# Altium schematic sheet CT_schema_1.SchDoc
size 594 x 458 mm
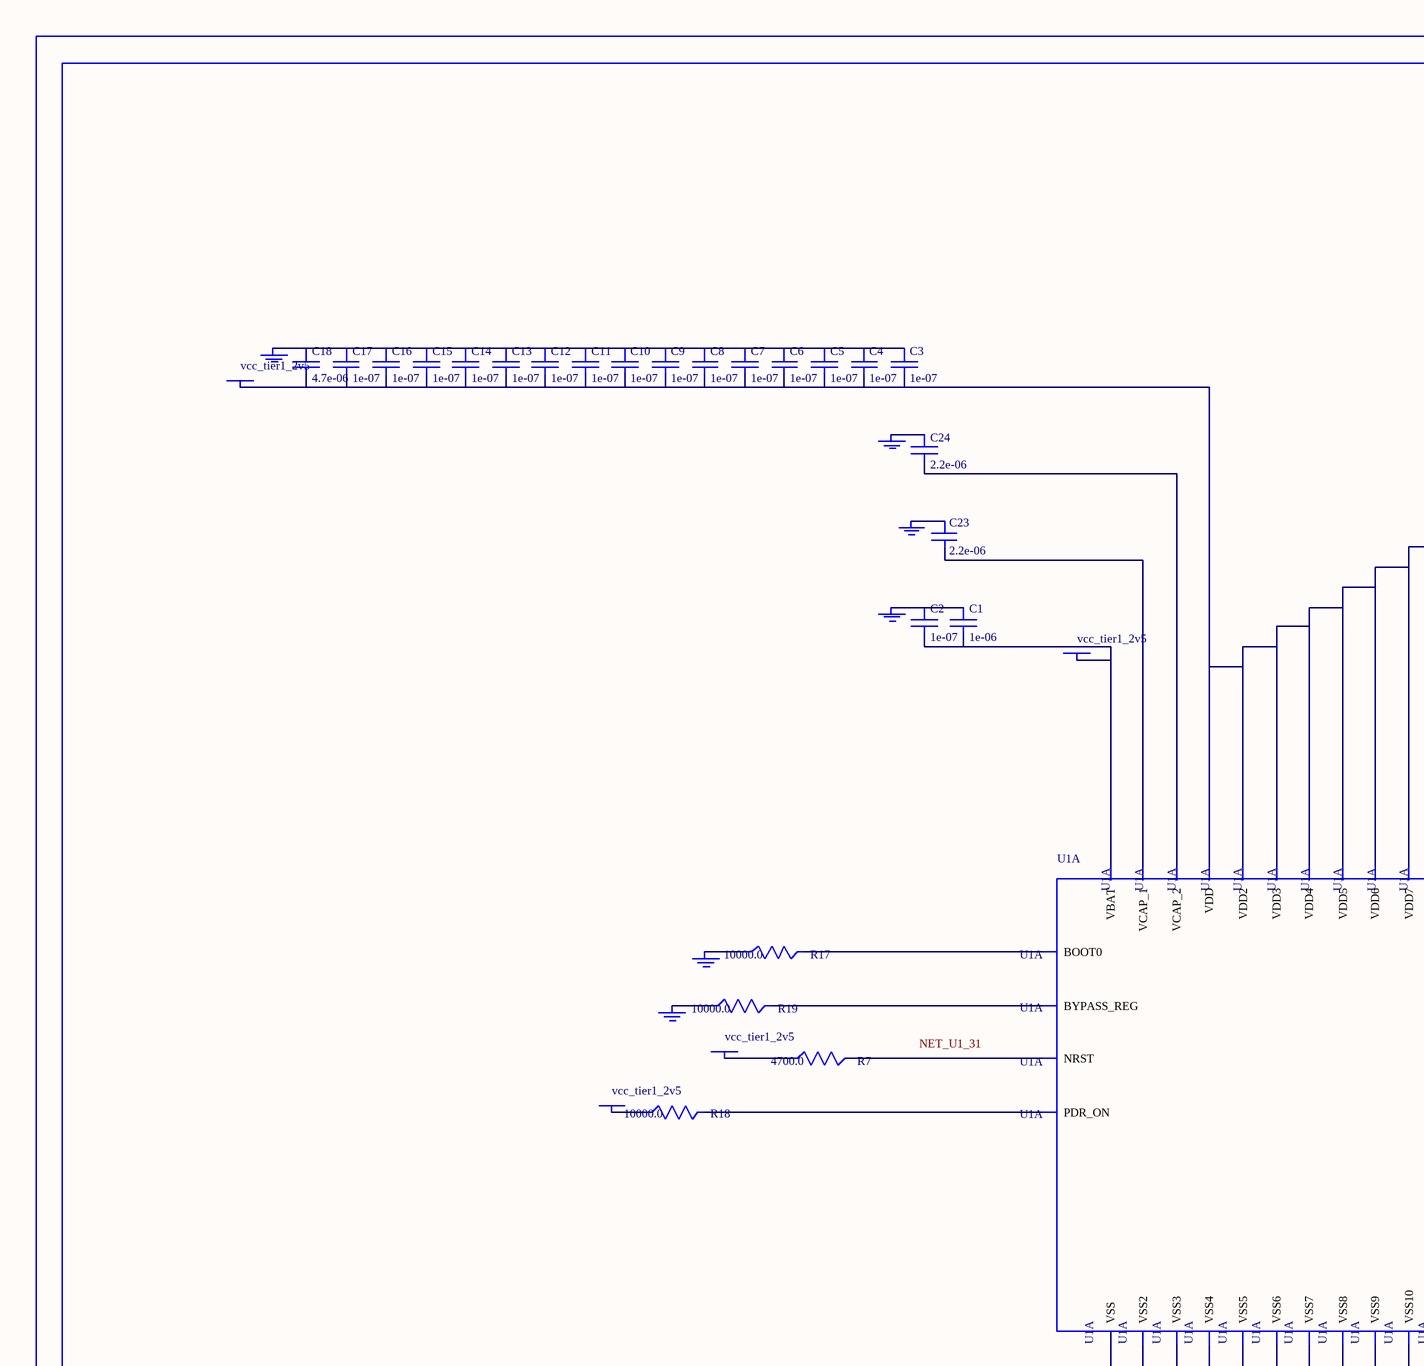
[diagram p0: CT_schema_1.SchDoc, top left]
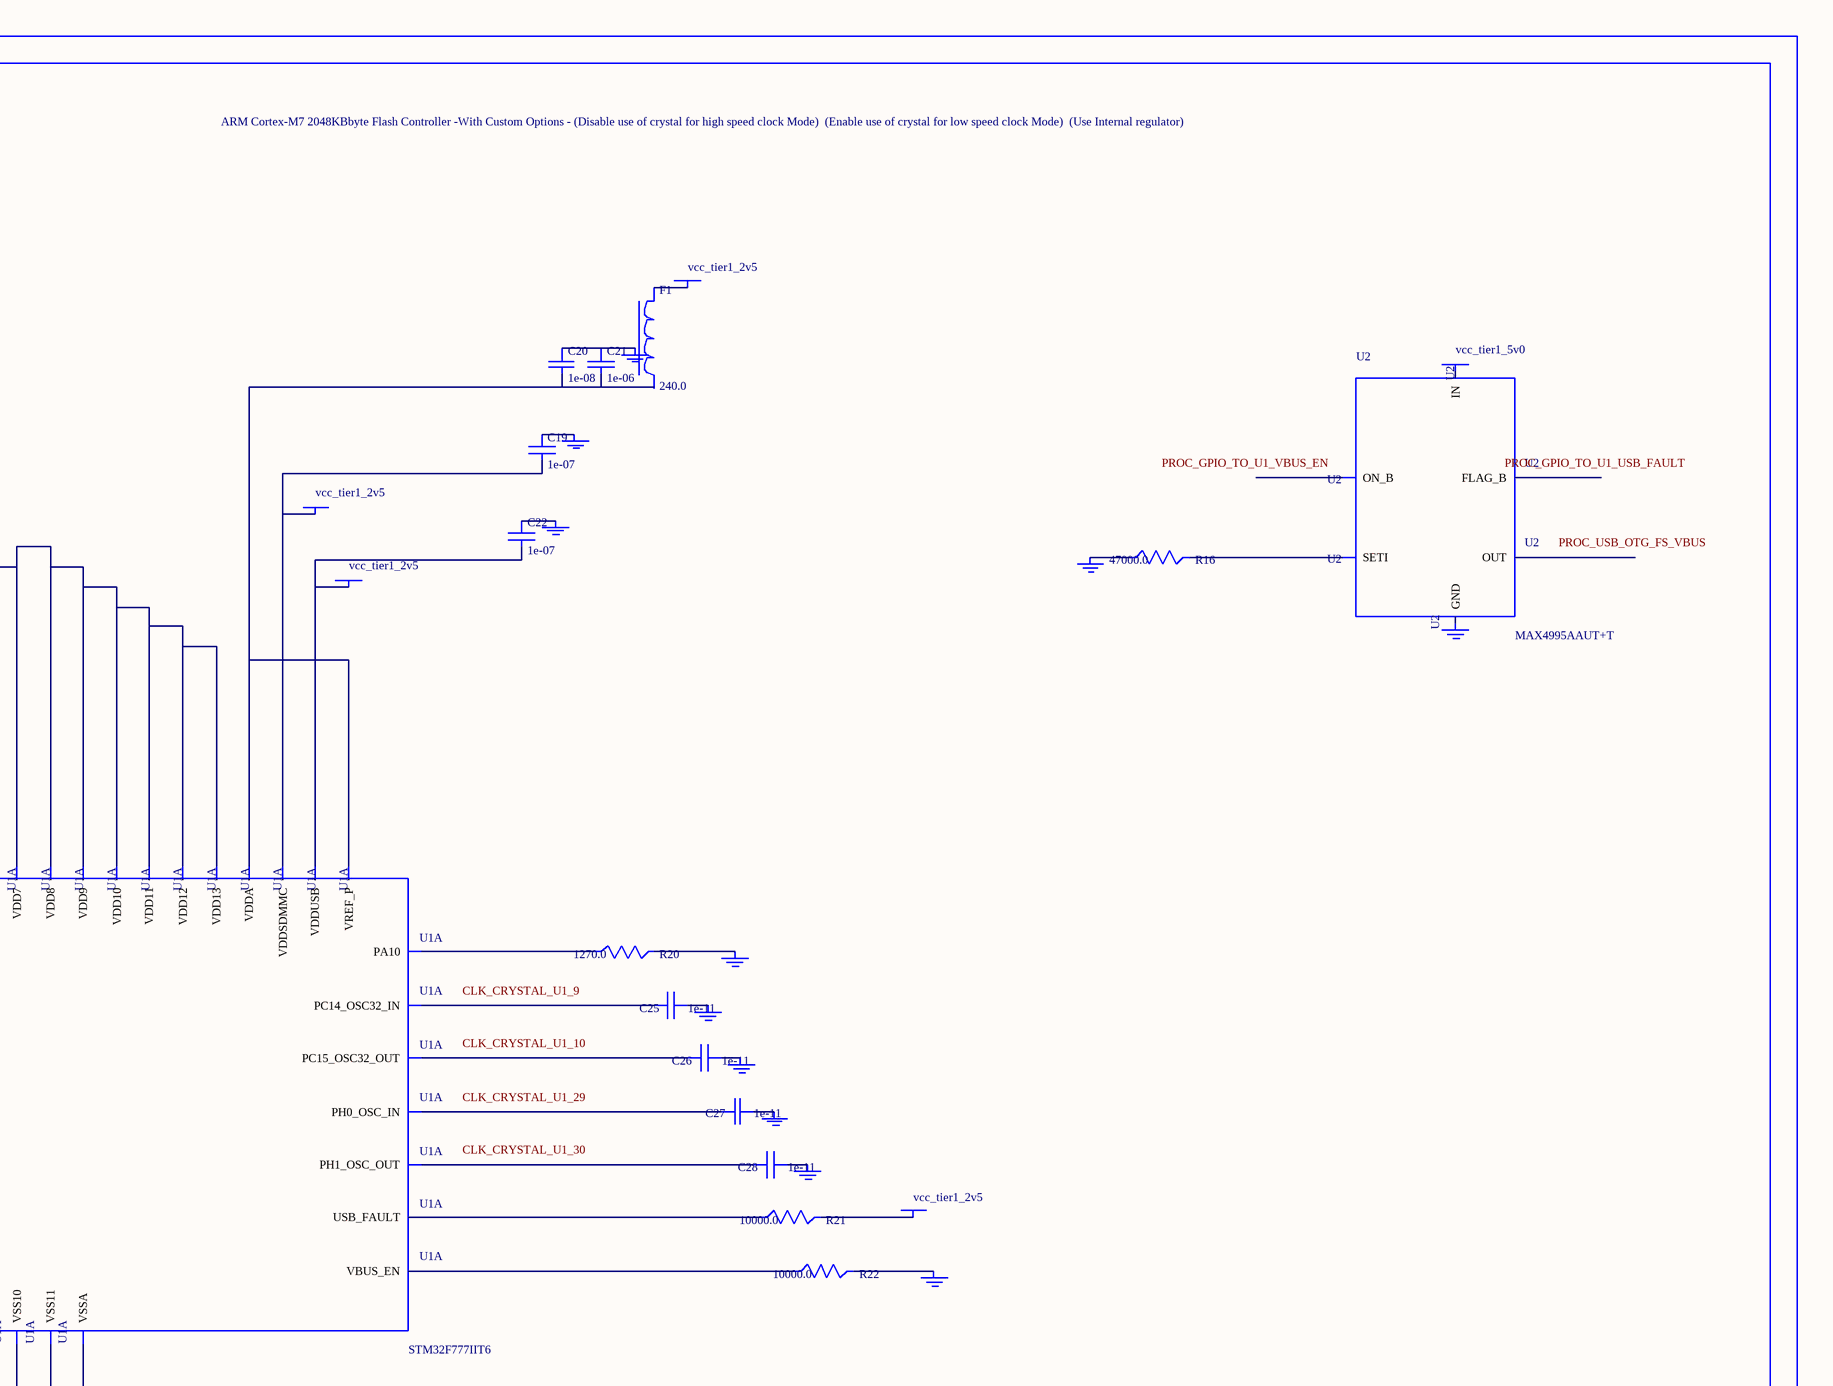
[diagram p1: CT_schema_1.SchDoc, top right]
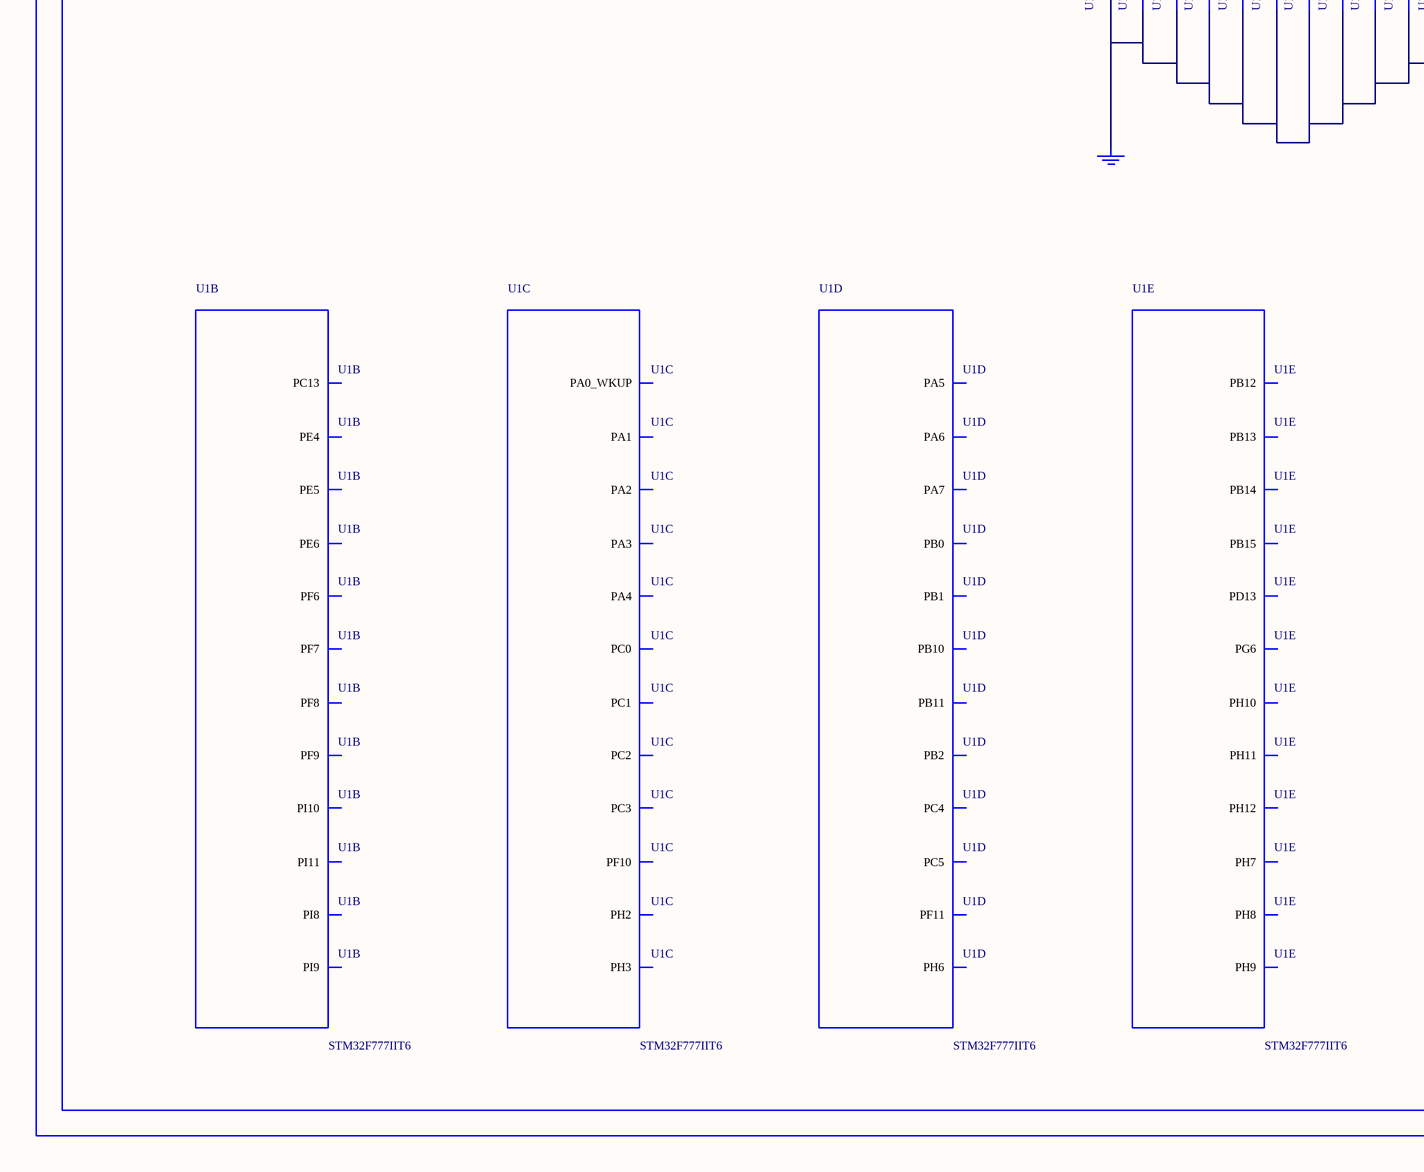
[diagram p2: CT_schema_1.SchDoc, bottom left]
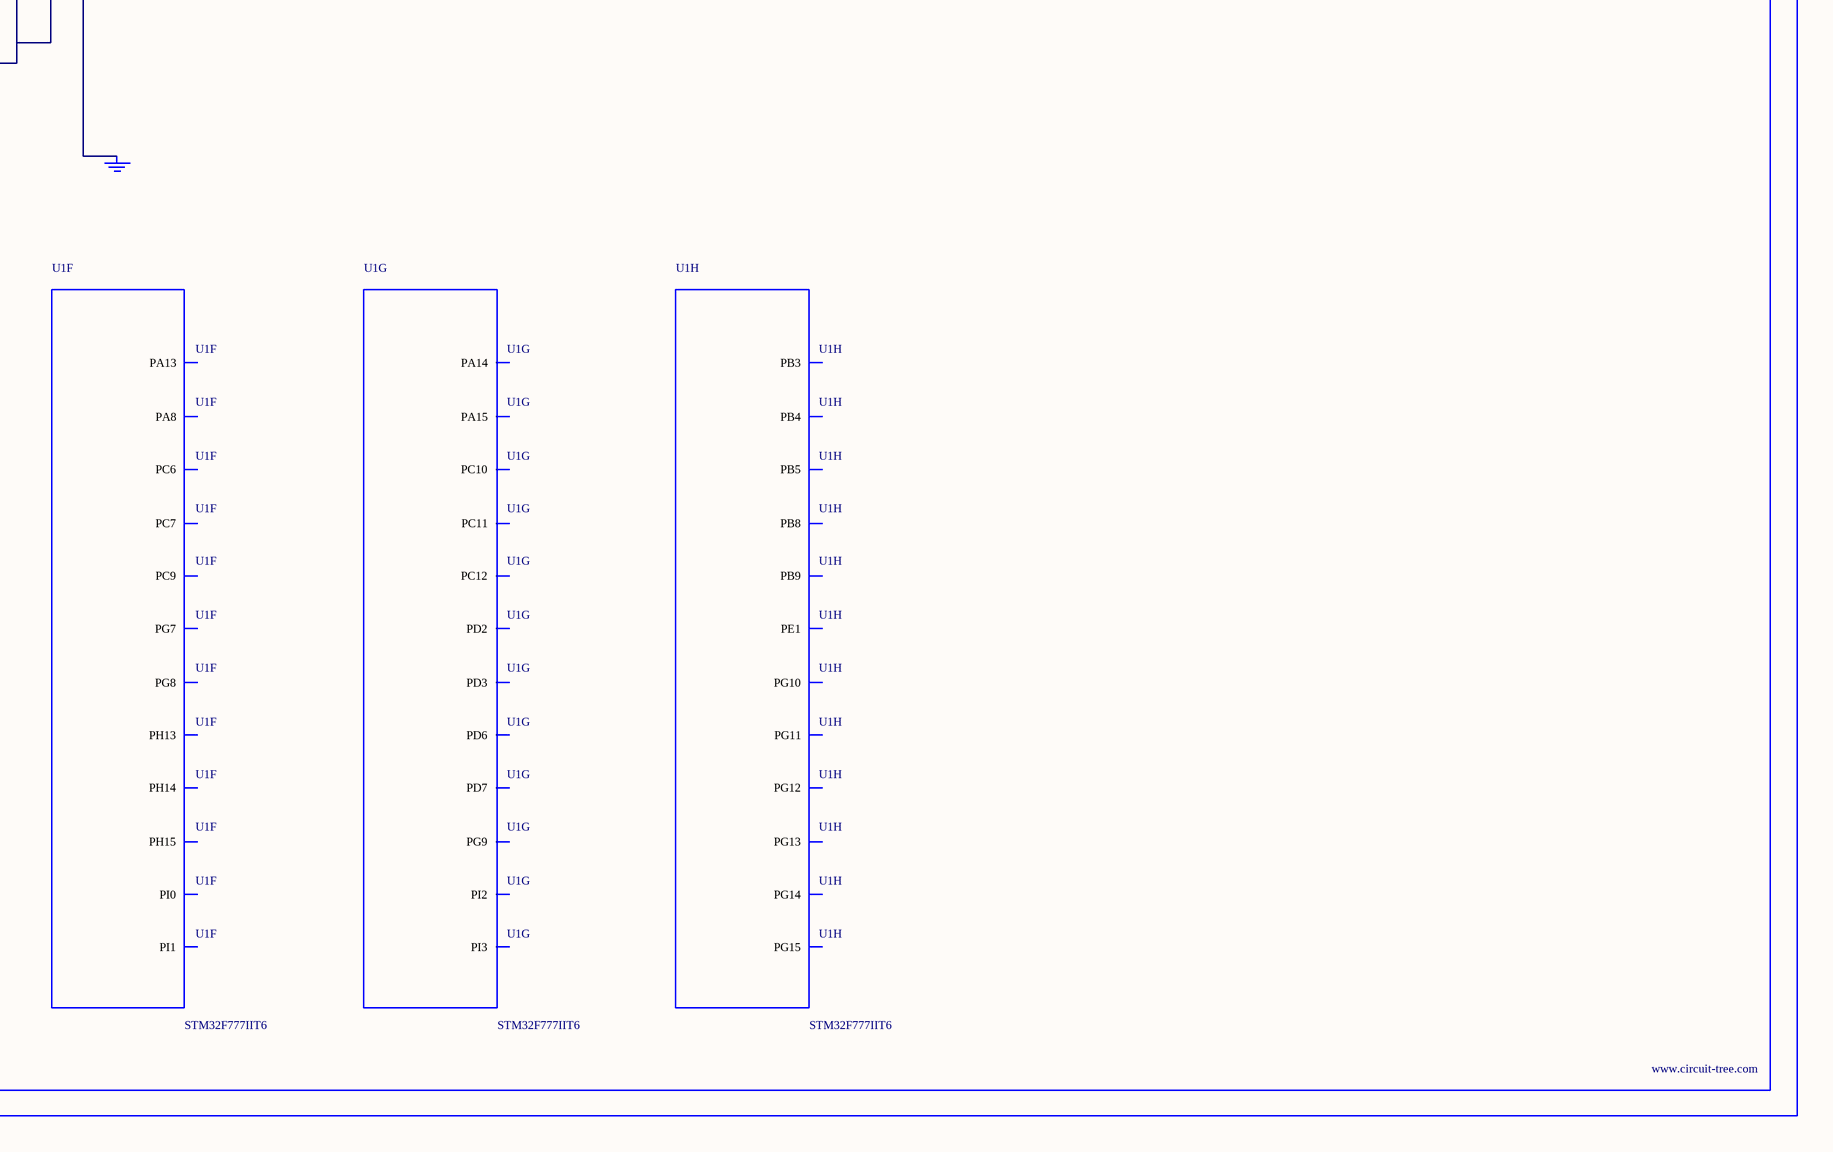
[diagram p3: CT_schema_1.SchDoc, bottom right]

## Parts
BORDER0  (no value)
C1  1e-06  [C0603]
C2  1e-07  [C0603]
C3  1e-07  [C0603]
C4  1e-07  [C0603]
C5  1e-07  [C0603]
C6  1e-07  [C0603]
C7  1e-07  [C0603]
C8  1e-07  [C0603]
C9  1e-07  [C0603]
C10  1e-07  [C0603]
C11  1e-07  [C0603]
C12  1e-07  [C0603]
C13  1e-07  [C0603]
C14  1e-07  [C0603]
C15  1e-07  [C0603]
C16  1e-07  [C0603]
C17  1e-07  [C0603]
C18  4.7e-06  [C0603]
C19  1e-07  [C0603]
C20  1e-08  [C0603]
C21  1e-06  [C0603]
C22  1e-07  [C0603]
C23  2.2e-06  [C0603]
C24  2.2e-06  [C0603]
C25  1e-11  [C0402]
C26  1e-11  [C0402]
C27  1e-11  [C0402]
C28  1e-11  [C0402]
F1  240.0  [L0603]
GND_INSTANCE_0_0  (no value)
GND_INSTANCE_0_1  (no value)
GND_INSTANCE_0_2  (no value)
GND_INSTANCE_0_3  (no value)
GND_INSTANCE_0_4  (no value)
GND_INSTANCE_0_5  (no value)
GND_INSTANCE_0_6  (no value)
GND_INSTANCE_0_7  (no value)
GND_INSTANCE_0_8  (no value)
GND_INSTANCE_0_9  (no value)
GND_INSTANCE_0_10  (no value)
GND_INSTANCE_0_11  (no value)
GND_INSTANCE_0_12  (no value)
GND_INSTANCE_0_13  (no value)
GND_INSTANCE_0_14  (no value)
GND_INSTANCE_0_15  (no value)
GND_INSTANCE_0_16  (no value)
GND_INSTANCE_0_17  (no value)
GND_INSTANCE_0_18  (no value)
POWER_INSTANCE_0_0  vcc_tier1_2v5
POWER_INSTANCE_0_1  vcc_tier1_2v5
POWER_INSTANCE_0_2  vcc_tier1_2v5
POWER_INSTANCE_0_3  vcc_tier1_2v5
POWER_INSTANCE_0_4  vcc_tier1_2v5
POWER_INSTANCE_0_5  vcc_tier1_2v5
POWER_INSTANCE_0_6  vcc_tier1_2v5
POWER_INSTANCE_0_7  vcc_tier1_2v5
POWER_INSTANCE_0_8  vcc_tier1_5v0
R7  4700.0  [R0603]
R16  47000.0  [R0603]
R17  10000.0  [R0603]
R18  10000.0  [R0603]
R19  10000.0  [R0603]
R20  1270.0  [R0603]
R21  10000.0  [R0603]
R22  10000.0  [R0603]
U1  STM32F777IIT6  [LQFP176]  (parts A,B,C,D,E,F,G,H of 15)
U2  MAX4995AAUT+T  [SOT-23-6]

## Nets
NetC1_1: C1.1 C2.1 GND_INSTANCE_0_1.0(GND)
NetC1_2: C1.2 C2.2 POWER_INSTANCE_0_1.0(PWR) U1.6(VBAT)
NetC3_1: C3.1 C4.1 C5.1 C6.1 C7.1 C8.1 C9.1 C10.1 C11.1 C12.1 C13.1 C14.1 C15.1 C16.1 C17.1 C18.1 GND_INSTANCE_0_4.0(GND)
NetC3_2: C3.2 C4.2 C5.2 C6.2 C7.2 C8.2 C9.2 C10.2 C11.2 C12.2 C13.2 C14.2 C15.2 C16.2 C17.2 C18.2 POWER_INSTANCE_0_2.0(PWR) U1.15(VDD) U1.23(VDD2) U1.36(VDD3) U1.49(VDD4) U1.62(VDD5) U1.72(VDD6) U1.82(VDD7) U1.91(VDD8) U1.103(VDD9) U1.127(VDD10) U1.136(VDD11) U1.159(VDD12) U1.172(VDD13)
NetC19_1: C19.1 GND_INSTANCE_0_14.0(GND)
NetC19_2: C19.2 POWER_INSTANCE_0_5.0(PWR) U1.149(VDDSDMMC)
NetC20_1: C20.1 C21.1 GND_INSTANCE_0_8.0(GND)
NetC20_2: C20.2 C21.2 U1.38(VREF_P) U1.39(VDDA)
NetC22_1: C22.1 GND_INSTANCE_0_11.0(GND)
NetC22_2: C22.2 POWER_INSTANCE_0_4.0(PWR) U1.114(VDDUSB)
NetC23_1: C23.1 GND_INSTANCE_0_10.0(GND)
NetC23_2: C23.2 U1.81(VCAP_1)
NetC24_1: C24.1 GND_INSTANCE_0_13.0(GND)
NetC24_2: C24.2 U1.125(VCAP_2)
NetC25_1: C25.1 GND_INSTANCE_0_2.0(GND)
NetC25_2: C25.2 U1.9(PC14_OSC32_IN)
NetC26_1: C26.1 GND_INSTANCE_0_3.0(GND)
NetC26_2: C26.2 U1.10(PC15_OSC32_OUT)
NetC27_1: C27.1 GND_INSTANCE_0_5.0(GND)
NetC27_2: C27.2 U1.29(PH0_OSC_IN)
NetC28_1: C28.1 GND_INSTANCE_0_6.0(GND)
NetC28_2: C28.2 U1.30(PH1_OSC_OUT)
NetF1_1: F1.1 POWER_INSTANCE_0_3.0(PWR)
NetGND_INSTANCE_0_0_0: GND_INSTANCE_0_0.0(GND) R22.2
NetGND_INSTANCE_0_7_0: GND_INSTANCE_0_7.0(GND) U1.37(VSSA)
NetGND_INSTANCE_0_9_0: GND_INSTANCE_0_9.0(GND) R19.1
NetGND_INSTANCE_0_12_0: GND_INSTANCE_0_12.0(GND) R20.2
NetGND_INSTANCE_0_15_0: GND_INSTANCE_0_15.0(GND) R17.1
NetGND_INSTANCE_0_16_0: GND_INSTANCE_0_16.0(GND) U1.14(VSS) U1.22(VSS2) U1.61(VSS3) U1.71(VSS4) U1.90(VSS5) U1.102(VSS6) U1.113(VSS7) U1.126(VSS8) U1.135(VSS9) U1.148(VSS10) U1.158(VSS11)
NetGND_INSTANCE_0_17_0: GND_INSTANCE_0_17.0(GND) R16.1
NetPOWER_INSTANCE_0_0_0: POWER_INSTANCE_0_0.0(PWR) R21.2
NetPOWER_INSTANCE_0_6_0: POWER_INSTANCE_0_6.0(PWR) R18.1
NetPOWER_INSTANCE_0_7_0: POWER_INSTANCE_0_7.0(PWR) R7.1
NetR7_2: R7.2 U1.31(NRST)
NetR16_2: R16.2 U2.3(SETI)
NetR17_2: R17.2 U1.166(BOOT0)
NetR18_2: R18.2 U1.171(PDR_ON)
NetR19_2: R19.2 U1.48(BYPASS_REG)
NetR20_1: R20.1 U1.121(PA10)
NetR21_1: R21.1 U1.2(USB_FAULT)
NetR22_1: R22.1 U1.1(VBUS_EN)

Not connected (* = marked no-connect by the designer): F1 2; GND_INSTANCE_0_18 0(GND); POWER_INSTANCE_0_8 0(PWR); U1 3(PE4) 4(PE5) 5(PE6) 7(PI8) 8(PC13) 11(PI9) 12(PI10) 13(PI11) 24(PF6) 25(PF7) 26(PF8) 27(PF9) 28(PF10) 32(PC0) 33(PC1) 34(PC2) 35(PC3) 40(PA0_WKUP) 41(PA1) 42(PA2) 43(PH2) 44(PH3) 47(PA3) 50(PA4) 51(PA5) 52(PA6) 53(PA7) 54(PC4) 55(PC5) 56(PB0) 57(PB1) 58(PB2) 59(PF11) 79(PB10) 80(PB11) 83(PH6) 84(PH7) 85(PH8) 86(PH9) 87(PH10) 88(PH11) 89(PH12) 92(PB12) 93(PB13) 94(PB14) 95(PB15) 101(PD13) 110(PG6) 111(PG7) 112(PG8) 115(PC6) 116(PC7) 118(PC9) 119(PA8) 124(PA13) 128(PH13) 129(PH14) 130(PH15) 131(PI0) 132(PI1) 133(PI2) 134(PI3) 137(PA14) 138(PA15) 139(PC10) 140(PC11) 141(PC12) 144(PD2) 145(PD3) 150(PD6) 151(PD7) 152(PG9) 153(PG10) 154(PG11) 155(PG12) 156(PG13) 157(PG14) 160(PG15) 161(PB3) 162(PB4) 163(PB5) 167(PB8) 168(PB9) 170(PE1); U2 1(OUT) 2(GND) 4(ON_B) 5(IN) 6(FLAG_B)

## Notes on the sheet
- Labels drawn without touching a wire or pin: CLK_CRYSTAL_U1_9, CLK_CRYSTAL_U1_10, CLK_CRYSTAL_U1_29, CLK_CRYSTAL_U1_30, NET_U1_31, PROC_GPIO_TO_U1_USB_FAULT, PROC_GPIO_TO_U1_VBUS_EN, PROC_USB_OTG_FS_VBUS

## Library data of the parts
BORDER0 = BORDER_PAGE0
C1 C21 = C0603C105K3RACTU
C2-C17 C19 C22 = 06035C104K4Z2A
C18 = GRM188R6YA475KE15D
C20 = 06035C103K4Z2A
C23 C24 = C0603C225K8RACTU
C25-C28 = C0402C100K3GACTU
F1 = Z0603C241ASMST
GND_INSTANCE_0_0-GND_INSTANCE_0_18 = GND
POWER_INSTANCE_0_0-POWER_INSTANCE_0_8 = PWR
R7 = RC0603JR-074K7L
R16 = RC0603JR-0747KL
R17-R19 R21 R22 = RC0603JR-0710KL
R20 = RC0603FR-071K27L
